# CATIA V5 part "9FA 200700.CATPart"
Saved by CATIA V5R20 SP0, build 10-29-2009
Part number: 9FA 200700
Revision: ANY
Definition: UNKNOWN
Nomenclature: 9FA 200700
Source: Unknown
Bounding box of the stored display mesh (mm): x -10 to 10, y 0.13 to 20.13, z -10 to 10
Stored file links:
  C:\Users\Utente\Desktop\IO LAVORO\3D X SITO CF\CUMSA\3D files FA\FA 200700\9FA 200700.CATPart
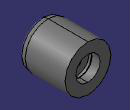
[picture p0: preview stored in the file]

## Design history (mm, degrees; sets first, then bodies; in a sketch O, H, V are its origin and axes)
Body1 "Redondeo1" (main body)
  Solid1: solid without history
